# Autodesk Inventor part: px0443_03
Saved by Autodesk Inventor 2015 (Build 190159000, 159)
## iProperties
Created: 2019-05
Part Number: px0443_03
Checked By: TraceParts S.A.
Material: Generic
Catalog Web Link: www.traceparts.com
Document SubType Name: Modeling
Designer: TraceParts
Density: 1 g/cm^3
Appearance: Default
Company: TraceParts S.A.
Author: TraceParts
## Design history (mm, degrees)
feature "px0443_03.ipt"
body "Solid1"
